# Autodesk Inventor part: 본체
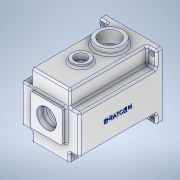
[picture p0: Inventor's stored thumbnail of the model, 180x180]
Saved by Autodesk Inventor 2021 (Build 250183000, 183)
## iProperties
Created: 2022-08
Part Number: 본체
Material: 알루미늄 6061
Document SubType Name: Modeling
Designer: Owner
Density: 2.7 g/cm^3
Appearance: 알루미늄 - 평지
Mass: 1791.21 g
Surface Area: 1184.03 cm^2
Volume: 663.41 cm^3
Author: Owner
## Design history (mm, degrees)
sketch "스케치2"
  geometry: L1 (55, 49)-(-55, 49); L2 (-55, 49)-(-55, -49); L3 (-55, -49)-(55, -49); L4 (55, -49)-(55, 49); L5 (55, 49)-(-55, -49); L6 (-55, 49)-(55, -49); 1 further point
  constraints: 12 end point, 2 midpoint, 2 parallel, 1 horizontal, 1 perpendicular
  dimensions: "d0" = 110 distance between parallel lines of L2 L4; "d1" = 98 distance between parallel lines of L1 L3
extrude "돌출1" new body sketch "스케치2" distance "d2" = 10; taper "d3" = 0 deg
sketch "스케치3"
  geometry: L1 (55, -49)-(-55, -49); L2 (-55, -49)-(-55, 49); L3 (-55, 49)-(55, 49); L4 (55, 49)-(55, -49); L5 (55, -49)-(-55, 49); L6 (-55, -49)-(55, 49); 1 further point
  constraints: 12 end point, 2 midpoint, 2 parallel, 1 horizontal, 1 perpendicular
  dimensions: "d4" = 98 distance between parallel lines of L3 L1; "d5" = 110 distance between parallel lines of L4 L2
extrude "돌출2" join sketch "스케치3" distance "d6" = 130; taper "d7" = 0 deg
sketch "스케치10"
  geometry: L1 (16, 140)-(0, 140); L2 (0, 140)-(0, 10); L3 (0, 10)-(16, 10); L4 (16, 10)-(16, 140); L5 (16, 140)-(0, 10); L6 (0, 140)-(16, 10); L7 (0, 0)-(98, 0) reference; L8 (0, 140)-(98, 140) reference; L9 (0, 0)-(0, 140) reference; L10 (98, 140)-(82, 140); L11 (82, 140)-(82, 10); L12 (82, 10)-(98, 10); L13 (98, 10)-(98, 140); L14 (98, 140)-(82, 10); L15 (82, 140)-(98, 10); L16 (98, 0)-(98, 140) reference; 5 further points
  constraints: 24 end point, 4 midpoint, 4 parallel, 2 horizontal, 2 perpendicular
  dimensions: "d45" = 10 distance between parallel lines of L7 L3; "d46" = 16 distance between parallel lines of L2 L4; "d47" = 0 distance between parallel lines of L8 L1; "d48" = 0 distance between parallel lines of L9 L2; "d50" = 16 distance between parallel lines of L11 L13; "d52" = 0 distance between parallel lines of L8 L10; "d53" = 10 distance between parallel lines of L7 L12; "d54" = 0 distance between parallel lines of L16 L13
extrude "돌출7" cut sketch "스케치10" distance "d55" = 27; taper "d56" = 0 deg
sketch "스케치11"
  geometry: L1 (17, 140)-(0, 140); L2 (0, 140)-(0, 10); L3 (0, 10)-(17, 10); L4 (17, 10)-(17, 140); L5 (17, 140)-(0, 10); L6 (0, 140)-(17, 10); L7 (0, 0)-(110, 0) reference; L8 (0, 140)-(83, 140) reference; L9 (0, 0)-(0, 140) reference; 2 further points
  constraints: 12 end point, 2 midpoint, 2 parallel, 1 horizontal, 1 perpendicular
  dimensions: "d57" = 10 distance between parallel lines of L7 L3; "d58" = 0 distance between parallel lines of L8 L1; "d59" = 17 distance between parallel lines of L2 L4; "d60" = 0 distance between parallel lines of L9 L2
extrude "돌출8" cut sketch "스케치11" distance "d61" = 17; taper "d62" = 0 deg
sketch "스케치12"
  geometry: L1 (110, 0)-(110, 140) reference; L2 (93, 10)-(110, 10); L3 (110, 10)-(110, 140); L4 (110, 140)-(93, 140); L5 (93, 140)-(93, 10); L6 (93, 10)-(110, 140); L7 (110, 10)-(93, 140); L8 (0, 0)-(110, 0) reference; L9 (27, 140)-(110, 140) reference; 3 further points
  constraints: 12 end point, 2 midpoint, 2 parallel, 1 horizontal, 1 perpendicular, 1 point on line
  dimensions: "d63" = 17 distance between parallel lines of L3 L5; "d64" = 10 distance between parallel lines of L8 L2; "d65" = 0 distance between parallel lines of L9 L4
extrude "돌출9" cut sketch "스케치12" distance "d66" = 17; taper "d67" = 0 deg
sketch "스케치14"
  geometry: L1 (-55, -49)-(-55, 49) reference; L2 (35.115, 23)-(48, 23); L3 (48, 23)-(48, -23); L4 (48, -23)-(35.115, -23); L5 (55, 49)-(55, -49) reference; A1 r 43.5 centre (-5, 0) between (30.253, 25.485) and (30.253, -25.485); A2 r 6 centre (35.115, 29) between (30.253, 25.485) and (35.115, 23); A3 r 6 centre (35.115, -29) between (35.115, -23) and (30.253, -25.485); 3 further points
  constraints: 8 point on circle, 6 end point, 4 tangent, 3 centre point, 2 perpendicular, 2 point on line, 1 equal radius, 1 horizontal
  dimensions: "d74" = 87 diameter of A1; "d75" = 50 distance from line of L1 A1.centre; "d76" = 7 distance between parallel lines of L5 L3; "d77" = 23 distance from line of point (0, 0) L2; "d78" = 23 distance from line of point (0, 0) L4; "d79" = 5 distance of point (0, 0) A1.centre; "d160" = 6 radius of A2 (derived)
extrude "돌출10" cut sketch "스케치14" distance "d80" = 9; taper "d81" = 0 deg
sketch "스케치15"
  geometry: L1 (-55, -49)-(-55, 49); L2 (30.143, 23)-(48, 23); L3 (48, 23)-(48, -23); L4 (48, -23)-(30.143, -23); L5 (55, 49)-(55, -49); L6 (45, -20)-(45, 20); L7 (45, 20)-(31.729, 20); L8 (31.729, -20)-(45, -20); A1 r 42 centre (-5, 0) between (30.143, 23) and (30.143, -23); A2 r 39 centre (-5, 0) between (26.832, 22.533) and (26.832, -22.533); A3 r 6 centre (31.729, 26) between (26.832, 22.533) and (31.729, 20); A4 r 6 centre (31.729, -26) between (31.729, -20) and (26.832, -22.533); 4 further points
  constraints: 16 end point, 10 point on circle, 4 centre point, 4 perpendicular, 4 tangent, 2 point on line, 1 equal radius, 1 horizontal, 3 other
  dimensions: "d82" = 84 diameter of A1; "d83" = 50 distance from line of L1 A1.centre; "d84" = 7 distance between parallel lines of L5 L3; "d85" = 23 distance from line of point (0, 0) L2; "d86" = 23 distance from line of point (0, 0) L4; "d87" = 5 distance of point (0, 0) A1.centre; "d88" = 3 distance between parallel lines of L3 L6; "d159" = 6 radius of A3
extrude "돌출11" cut sketch "스케치15" distance "d89" = 114; taper "d90" = 0 deg
node "작업 평면1"
sketch "스케치16"
  geometry: L1 (55, -49)-(55, 49) reference; L2 (1.006, 35.778)-(1.006, 38.795); L3 (8.994, 35.778)-(9.161, 38.777); L4 (1.006, -35.778)-(1.006, -38.795); L5 (8.994, -35.778)-(9.161, -38.777); A1 r 4 centre (5, 36) between (1.006, 36.222) and (8.994, 35.778); A2 r 4 centre (5, -36) between (8.994, -35.778) and (1.006, -36.222); A3 r 36 centre (5, 0) between (5, -36) and (5, 36); A4 r 39 centre (5, 0) between (-26.832, -22.533) and (-26.832, 22.533) reference; 4 further points
  constraints: 17 point on circle, 8 end point, 3 centre point, 2 point on line, 2 tangent, 2 vertical
  dimensions: "d92" = 50 distance from line of L1 A2.centre; "d93" = 50 distance from line of L1 A1.centre; "d94" = 8 diameter of A1; "d95" = 8 diameter of A2; "d96" = 72 diameter of A3; "d97" = 50 distance from line of L1 A3.centre; "d98" = 0 vertical distance of point (0, 0) A3.centre
extrude "돌출12" join sketch "스케치16" distance "d99" = 121; taper "d100" = 0 deg
sketch "스케치17"
  geometry: A1 r 4 centre (-5, -36) between (-1.006, -35.778) and (-8.994, -35.778) reference; A2 r 4 centre (-5, 36) between (-8.994, 35.778) and (-1.006, 35.778) reference; 3 further points
  constraints: 2 coincident
hole "구멍1" sketch "스케치17" at (-5, 36), (-5, -36) diameter "d101" = 3.242; stored, may be unused: countersink angle "d105" = 90 deg, drill point angle "d107" = 118 deg; dims "d102" = 8, "d103" = 4, "d104" = 2, "d106" = 11.8
sketch "스케치18"
  geometry: L1 (0, 0)-(98, 0) reference; C1 r 22.5 at (49, 40); 2 further points
  constraints: 1 centre point, 1 midpoint, 1 vertical alignment
  dimensions: "d108" = 45 diameter of C1; "d109" = 40 distance of point (49, 0) C1.centre
extrude "돌출13" join sketch "스케치18" distance "d110" = 10; taper "d111" = 0 deg
sketch "스케치19"
  geometry: L1 (0, 0)-(98, 0) reference; C1 r 15 at (49, 89); C2 r 22.5 at (49, 40) reference; 2 further points
  constraints: 1 centre point, 1 midpoint, 1 vertical alignment
  dimensions: "d112" = 30 diameter of C1; "d113" = 49 distance of C2.centre C1.centre
extrude "돌출14" join sketch "스케치19" distance "d114" = 5; taper "d115" = 0 deg
sketch "스케치20"
  geometry: C1 r 15 at (0, 0) reference; C2 r 10 at (0, 0); 1 further point
  constraints: 1 centre point, 1 coincident
  dimensions: "d116" = 20 diameter of C2
extrude "돌출15" cut sketch "스케치20" stored distance "d117" = 5; taper "d118" = 0 deg
sketch "스케치21"
  geometry: C1 r 22.5 at (0, 0) reference; 2 further points
  constraints: 1 coincident
hole "구멍2" sketch "스케치21" at (0, 0) diameter "d119" = 33.376; stored, may be unused: countersink angle "d123" = 90 deg, drill point angle "d125" = 118 deg; dims "d120" = 70, "d121" = 4, "d122" = 2, "d124" = 77.3
sketch "스케치22"
  geometry: C1 r 10 at (20, 80) reference; C2 r 15 at (20, 80); 1 further point
  constraints: 1 centre point, 1 coincident
  dimensions: "d126" = 30 diameter of C2
extrude "돌출16" cut sketch "스케치22" distance "d127" = 5; taper "d128" = 0 deg
sketch "스케치23"
  geometry: L1 (27, 27)-(-27, 27); L2 (-27, 27)-(-27, -27); L3 (-27, -27)-(27, -27); L4 (27, -27)-(27, 27); L5 (27, 27)-(-27, -27); L6 (-27, 27)-(27, -27); 1 further point
  constraints: 12 end point, 2 midpoint, 2 parallel, 1 horizontal, 1 perpendicular
  dimensions: "d129" = 54 distance between parallel lines of L2 L4; "d130" = 54 distance between parallel lines of L1 L3
extrude "돌출17" join sketch "스케치23" distance "d131" = 7; taper "d132" = 0 deg
sketch "스케치25"
  geometry: 2 further points
  constraints: 1 coincident
hole "구멍3" sketch "스케치25" at (0, 0) diameter "d134" = 28; stored, may be unused: countersink angle "d138" = 90 deg, drill point angle "d140" = 118 deg; dims "d135" = 70, "d136" = 32, "d137" = 8.3, "d139" = 77.3
sketch "스케치26"
  geometry: C1 r 17.5 at (0, 0); 1 further point
  constraints: 1 centre point, 1 coincident
  dimensions: "d141" = 35 diameter of C1
extrude "돌출18" cut sketch "스케치26" distance "d142" = 10; taper "d143" = 0 deg
sketch "스케치27"
  geometry: C1 r 11 at (-29, 0); C2 r 16 at (0, 0) reference; C3 r 17.5 at (0, 0) reference; 1 further point
  constraints: 1 centre point, 1 horizontal alignment
  dimensions: "d144" = 22 diameter of C1; "d145" = 29 distance of C1.centre point (0, 0)
extrude "돌출19" cut sketch "스케치27" distance "d146" = 7; taper "d147" = 0 deg
sketch "스케치28"
  geometry: C1 r 11 at (0, 0) reference; C2 r 9.5 at (0, 0); 1 further point
  constraints: 1 centre point, 1 coincident
  dimensions: "d148" = 19 diameter of C2
extrude "돌출20" cut sketch "스케치28" distance "d149" = 3; taper "d150" = 0 deg
fillet "모깎기1" dims "d151" = 0.3
chamfer "모따기1" distance "d152" = 0.8; stored, may be unused: second distance "d153" = 2, angle "d154" = 30 deg
fillet "모깎기2" dims "d155" = 0.3
fillet "모깎기3" dims "d156" = 3
fillet "모깎기4" dims "d157" = 3
fillet "모깎기5" dims "d158" = 3
chamfer "모따기2" distance "d161" = 1; stored, may be unused: second distance "d162" = 2, angle "d163" = 30 deg
fillet "모깎기6" dims "d164" = 3
sketch "스케치31"
  geometry: L1 (21, -16)-(-6, -16) reference; L2 (24, 3)-(24, -13) reference; C1 r 4.5 at (17, -9); 1 further point
  constraints: 1 centre point
  dimensions: "d165" = 7 distance from line of L1 C1.centre; "d166" = 7 distance from line of L2 C1.centre; "d167" = 9 diameter of C1
extrude "돌출21" cut sketch "스케치31" extent not by distance; stored distance "d168" = 3; taper "d169" = 0 deg
fillet "모깎기7" dims "d170" = 3
fillet "모깎기8" dims "d171" = 3
fillet "모깎기11" dims "d174" = 3
sketch "스케치32"
  geometry: L1 (80, 13)-(80, 137) reference; L2 (77, 140)-(17, 140) reference; 2 further points
  constraints: 1 other
  dimensions: "d175" = 33 distance from line of L1 point (47, 75); "d176" = 65 distance from line of L2 point (47, 75)
feature "엠보싱1" sketch "스케치32" dims "d177" = 0.5, "d178" = 0
fillet "모깎기12" dims "d179" = 3
fillet "모깎기14" dims "d181" = 3
fillet "모깎기15" dims "d182" = 3
fillet "모깎기16" dims "d183" = 3
fillet "모깎기17" dims "d184" = 3
chamfer "모따기3" distance "d185" = 1; stored, may be unused: second distance "d186" = 2, angle "d187" = 30 deg
node "솔리드1"
mirror "미러1"
mirror "미러2"
feature "A9D066F2-1C7D-4E18-AEED-F7BC21143FA4" dims "d134" = 28, "d135" = 70, "d136" = 32, "d137" = 8.3, "d138" = 90 deg, "d139" = 77.3, "d140" = 118 deg
other parameters: "d91" = 9
